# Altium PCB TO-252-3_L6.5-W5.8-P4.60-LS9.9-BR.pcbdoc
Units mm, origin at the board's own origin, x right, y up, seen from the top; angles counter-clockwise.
Board outline 23.56 x 19.45 mm, 2 copper layers (Top Layer, Bottom Layer), stack 0 mm thick; 1 components, 0 nets, 3 pads, 0 vias.
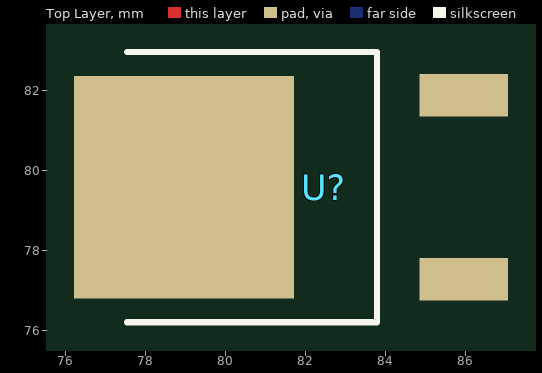
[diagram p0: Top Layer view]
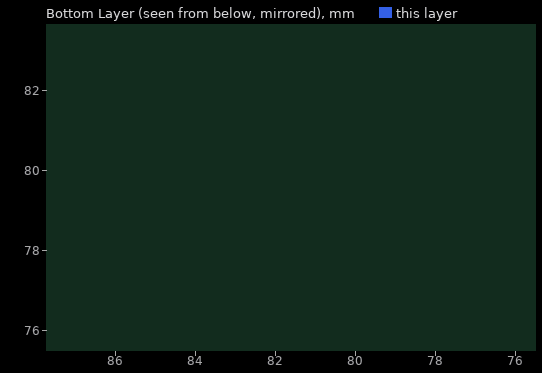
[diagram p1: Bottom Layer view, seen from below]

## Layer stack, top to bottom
Top Layer: signal copper (thickness not stored)
Bottom Layer: signal copper (thickness not stored)

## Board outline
93.406,69.85 69.85,69.85 69.85,89.302 93.406,89.302

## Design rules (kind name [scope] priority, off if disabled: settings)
PasteMaskExpansion "Paste Mask Expansion" [All] p1: expansion=0
SolderMaskExpansion "Solder Mask Expansion" [IsVia] p1: expansion=-25.4 istentingtop=TRUE
SolderMaskExpansion "Solder Mask Expansion" [All] p2: expansion=0.051 istentingtop=FALSE

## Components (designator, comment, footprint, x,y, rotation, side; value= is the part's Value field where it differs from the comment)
U? "" TO-252-3_L6.5-W5.8-P4.60-LS9.9-BR 82.449,79.576 r0 top

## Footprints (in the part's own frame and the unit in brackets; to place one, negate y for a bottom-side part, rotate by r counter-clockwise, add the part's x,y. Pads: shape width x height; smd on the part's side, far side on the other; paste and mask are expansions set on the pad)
TO-252-3_L6.5-W5.8-P4.60-LS9.9-BR [mm]
  rect 2.218x1.064 smd: 1(3.498,-2.3) 3(3.498,2.3)
  rect 5.5x5.554 smd: 2(-3.499,0)
  silkscreen extent -4.92,-3.38 1.33,3.38

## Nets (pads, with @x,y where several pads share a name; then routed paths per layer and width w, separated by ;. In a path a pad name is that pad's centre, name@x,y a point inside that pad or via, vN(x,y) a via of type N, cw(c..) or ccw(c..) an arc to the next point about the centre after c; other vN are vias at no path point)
pads on no net: U?.1 U?.2 U?.3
